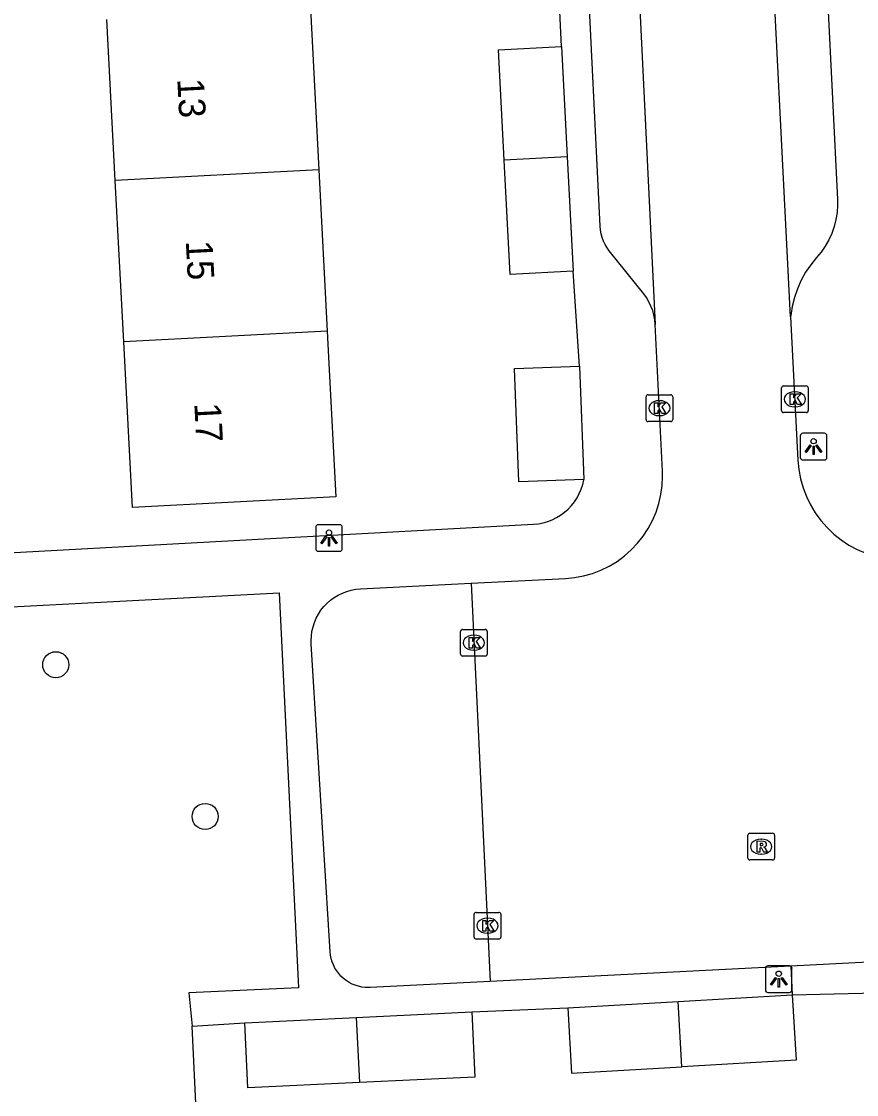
# Model space of a CAD drawing. Extents: x 161084 to 161928, y 385355 to 386522.
# Drawn here: x 161567.76 to 161599.07, y 385663.68 to 385703.9 of the extents above; entities that cross this region are included whole.
import ezdxf

# ---------------------------------------------------------------- set-up
doc = ezdxf.new("R2010")
doc.units = 0
for name, color, linetype in [('IMGEO_Boom', 7, 'Continuous'), ('IMGEO_Groenvoorziening', 7, 'Continuous'), ('IMGEO_Hek', 7, 'Continuous'), ('IMGEO_Kolk', 7, 'Continuous'), ('IMGEO_Lichtpunt', 7, 'Continuous'), ('IMGEO_Pand', 7, 'Continuous'), ('IMGEO_Pand_nummerreeks', 7, 'Continuous'), ('IMGEO_Rijbaan_lokaal_open', 7, 'Continuous'), ('IMGEO_Rioolput', 7, 'Continuous'), ('IMGEO_Voetpad_open', 7, 'Continuous')]:
    doc.layers.add(name, color=color, linetype=linetype)

msp = doc.modelspace()

# ---------------------------------------------------------------- linework, layer by layer
at = {"layer": 'IMGEO_Boom'}
for centre in [(161569.044, 385679.792), (161574.644, 385674.104)]:
    msp.add_circle(centre, 0.489, dxfattribs=at)
at = {"layer": 'IMGEO_Groenvoorziening'}
msp.add_lwpolyline([(161574.665, 385655.497), (161574.152, 385666.247)], dxfattribs=at)
at = {"layer": 'IMGEO_Hek'}
msp.add_lwpolyline([(161574.665, 385655.497), (161574.152, 385666.247)], dxfattribs=at)
at = {"layer": 'IMGEO_Kolk'}
for p, q in [((161596.255, 385689.315), (161596.255, 385690.167)), ((161596.33, 385690.241), (161597.182, 385690.241)), ((161597.256, 385690.167), (161597.256, 385689.315)), ((161591.174, 385688.982), (161591.174, 385689.834)), ((161591.249, 385689.908), (161592.101, 385689.908)), ((161591.662, 385689.688), (161591.687, 385689.688)), ((161592.175, 385689.834), (161592.175, 385688.982)), ((161596.743, 385690.021), (161596.768, 385690.021)), ((161596.766, 385689.461), (161596.741, 385689.461)), ((161592.101, 385688.908), (161591.249, 385688.908)), ((161591.685, 385689.128), (161591.66, 385689.128)), ((161597.182, 385689.241), (161596.33, 385689.241)), ((161584.22, 385680.189), (161584.22, 385681.041)), ((161584.295, 385681.115), (161585.147, 385681.115)), ((161584.708, 385680.895), (161584.733, 385680.895)), ((161585.221, 385681.041), (161585.221, 385680.189)), ((161585.147, 385680.115), (161584.295, 385680.115)), ((161584.731, 385680.335), (161584.706, 385680.335)), ((161584.73, 385669.585), (161584.73, 385670.437)), ((161584.805, 385670.511), (161585.657, 385670.511)), ((161585.731, 385670.437), (161585.731, 385669.585)), ((161585.218, 385670.291), (161585.243, 385670.291)), ((161585.241, 385669.731), (161585.216, 385669.731)), ((161585.657, 385669.511), (161584.805, 385669.511))]:
    msp.add_line(p, q, dxfattribs=at)
for points in [[(161596.255, 385689.315), (161596.255, 385690.167)], [(161596.33, 385690.241), (161597.182, 385690.241)], [(161597.256, 385690.167), (161597.256, 385689.315)], [(161591.174, 385688.982), (161591.174, 385689.834)], [(161591.249, 385689.908), (161592.101, 385689.908)], [(161592.175, 385689.834), (161592.175, 385688.982)], [(161596.576, 385689.941), (161596.699, 385689.941), (161596.699, 385689.79), (161596.829, 385689.941), (161596.993, 385689.941), (161596.847, 385689.79), (161597, 385689.541), (161596.848, 385689.541), (161596.763, 385689.705), (161596.699, 385689.638), (161596.699, 385689.541), (161596.576, 385689.541), (161596.576, 385689.941)], [(161591.495, 385689.608), (161591.618, 385689.608), (161591.618, 385689.457), (161591.748, 385689.608), (161591.912, 385689.608), (161591.766, 385689.457), (161591.919, 385689.208), (161591.767, 385689.208), (161591.682, 385689.372), (161591.618, 385689.305), (161591.618, 385689.208), (161591.495, 385689.208), (161591.495, 385689.608)], [(161592.101, 385688.908), (161591.249, 385688.908)], [(161597.182, 385689.241), (161596.33, 385689.241)], [(161584.22, 385680.189), (161584.22, 385681.041)], [(161584.295, 385681.115), (161585.147, 385681.115)], [(161584.541, 385680.815), (161584.664, 385680.815), (161584.664, 385680.664), (161584.794, 385680.815), (161584.958, 385680.815), (161584.812, 385680.664), (161584.965, 385680.415), (161584.813, 385680.415), (161584.728, 385680.579), (161584.664, 385680.512), (161584.664, 385680.415), (161584.541, 385680.415), (161584.541, 385680.815)], [(161585.221, 385681.041), (161585.221, 385680.189)], [(161585.147, 385680.115), (161584.295, 385680.115)], [(161584.73, 385669.585), (161584.73, 385670.437)], [(161584.805, 385670.511), (161585.657, 385670.511)], [(161585.731, 385670.437), (161585.731, 385669.585)], [(161585.051, 385670.211), (161585.174, 385670.211), (161585.174, 385670.06), (161585.304, 385670.211), (161585.468, 385670.211), (161585.322, 385670.06), (161585.475, 385669.811), (161585.323, 385669.811), (161585.238, 385669.975), (161585.174, 385669.908), (161585.174, 385669.811), (161585.051, 385669.811), (161585.051, 385670.211)], [(161585.657, 385669.511), (161584.805, 385669.511)]]:
    msp.add_lwpolyline(points, dxfattribs=at)
for centre, start, end in [((161596.332, 385690.165), 91.552, 178.448), ((161596.332, 385690.165), 91.552, 178.448), ((161597.18, 385690.165), 1.552, 88.448), ((161597.18, 385690.165), 1.552, 88.448), ((161591.251, 385689.832), 91.552, 178.448), ((161591.251, 385689.832), 91.552, 178.448), ((161592.099, 385689.832), 1.552, 88.448), ((161592.099, 385689.832), 1.552, 88.448), ((161596.332, 385689.317), 181.552, 268.448), ((161596.332, 385689.317), 181.552, 268.448), ((161597.18, 385689.317), 271.552, 358.448), ((161597.18, 385689.317), 271.552, 358.448), ((161591.251, 385688.984), 181.552, 268.448), ((161591.251, 385688.984), 181.552, 268.448), ((161592.099, 385688.984), 271.552, 358.448), ((161592.099, 385688.984), 271.552, 358.448), ((161584.297, 385681.039), 91.552, 178.448), ((161584.297, 385681.039), 91.552, 178.448), ((161585.145, 385681.039), 1.552, 88.448), ((161585.145, 385681.039), 1.552, 88.448), ((161584.297, 385680.191), 181.552, 268.448), ((161584.297, 385680.191), 181.552, 268.448), ((161585.145, 385680.191), 271.552, 358.448), ((161585.145, 385680.191), 271.552, 358.448), ((161584.807, 385670.435), 91.552, 178.448), ((161584.807, 385670.435), 91.552, 178.448), ((161585.655, 385670.435), 1.552, 88.448), ((161585.655, 385670.435), 1.552, 88.448), ((161584.807, 385669.587), 181.552, 268.448), ((161584.807, 385669.587), 181.552, 268.448), ((161585.655, 385669.587), 271.552, 358.448), ((161585.655, 385669.587), 271.552, 358.448)]:
    msp.add_arc(centre, 0.0765, start, end, dxfattribs=at)
for centre, major_axis, ratio, start_param, end_param in [((161591.661, 385689.408), (-0.387, 0.002), 0.722429, 4.712389, 7.853982), ((161591.686, 385689.408), (-0.39, 0.002), 0.717154, 1.570796, 4.712389), ((161596.742, 385689.741), (-0.387, 0.002), 0.722429, 4.712389, 7.853982), ((161596.767, 385689.741), (-0.39, 0.002), 0.717154, 1.570796, 4.712389), ((161584.707, 385680.615), (-0.387, 0.002), 0.722429, 4.712389, 7.853982), ((161584.732, 385680.615), (-0.39, 0.002), 0.717154, 1.570796, 4.712389), ((161585.217, 385670.011), (-0.387, 0.002), 0.722429, 4.712389, 7.853982), ((161585.242, 385670.011), (-0.39, 0.002), 0.717154, 1.570796, 4.712389)]:
    msp.add_ellipse(centre, major_axis=major_axis, ratio=ratio, start_param=start_param, end_param=end_param, dxfattribs=at)
at = {"layer": 'IMGEO_Lichtpunt'}
for p, q in [((161597.861, 385688.466), (161597.053, 385688.466)), ((161597.861, 385688.466), (161597.053, 385688.466)), ((161596.959, 385688.371), (161596.959, 385687.564)), ((161596.959, 385688.371), (161596.959, 385687.564)), ((161597.955, 385687.564), (161597.955, 385688.371)), ((161597.955, 385687.564), (161597.955, 385688.371)), ((161597.053, 385687.47), (161597.861, 385687.47)), ((161597.053, 385687.47), (161597.861, 385687.47)), ((161578.789, 385684.944), (161578.789, 385684.137)), ((161578.789, 385684.944), (161578.789, 385684.137)), ((161579.691, 385685.039), (161578.883, 385685.039)), ((161579.691, 385685.039), (161578.883, 385685.039)), ((161579.785, 385684.137), (161579.785, 385684.944)), ((161579.785, 385684.137), (161579.785, 385684.944)), ((161578.883, 385684.043), (161579.691, 385684.043)), ((161578.883, 385684.043), (161579.691, 385684.043)), ((161595.651, 385668.411), (161595.651, 385667.604)), ((161595.651, 385668.411), (161595.651, 385667.604)), ((161596.553, 385668.506), (161595.745, 385668.506)), ((161596.553, 385668.506), (161595.745, 385668.506)), ((161596.647, 385667.604), (161596.647, 385668.411)), ((161596.647, 385667.604), (161596.647, 385668.411)), ((161595.745, 385667.51), (161596.553, 385667.51)), ((161595.745, 385667.51), (161596.553, 385667.51))]:
    msp.add_line(p, q, dxfattribs=at)
for points in [[(161597.333, 385688.035), (161597.372, 385688.007), (161597.184, 385687.745), (161597.146, 385687.772), (161597.333, 385688.035)], [(161597.435, 385687.987), (161597.482, 385687.987), (161597.482, 385687.665), (161597.435, 385687.665), (161597.435, 385687.987)], [(161597.545, 385688.007), (161597.583, 385688.034), (161597.77, 385687.772), (161597.731, 385687.744), (161597.545, 385688.007)], [(161579.163, 385684.608), (161579.202, 385684.58), (161579.014, 385684.318), (161578.976, 385684.345), (161579.163, 385684.608)], [(161579.265, 385684.56), (161579.312, 385684.56), (161579.312, 385684.238), (161579.265, 385684.238), (161579.265, 385684.56)], [(161579.375, 385684.58), (161579.413, 385684.607), (161579.6, 385684.345), (161579.561, 385684.317), (161579.375, 385684.58)], [(161596.025, 385668.075), (161596.064, 385668.047), (161595.876, 385667.785), (161595.838, 385667.812), (161596.025, 385668.075)], [(161596.127, 385668.027), (161596.174, 385668.027), (161596.174, 385667.705), (161596.127, 385667.705), (161596.127, 385668.027)], [(161596.237, 385668.047), (161596.275, 385668.074), (161596.462, 385667.812), (161596.423, 385667.784), (161596.237, 385668.047)]]:
    msp.add_lwpolyline(points, dxfattribs=at)
for centre in [(161597.458, 385688.169), (161579.288, 385684.742), (161596.15, 385668.209)]:
    msp.add_circle(centre, 0.0994, dxfattribs=at)
for centre, start, end in [((161597.053, 385688.371), 90, 180), ((161597.053, 385688.371), 90, 180), ((161597.861, 385688.371), 0, 90), ((161597.861, 385688.371), 0, 90), ((161597.053, 385687.564), 180, 270), ((161597.053, 385687.564), 180, 270), ((161597.861, 385687.564), 270, 0), ((161597.861, 385687.564), 270, 360), ((161578.883, 385684.944), 90, 180), ((161578.883, 385684.944), 90, 180), ((161579.691, 385684.944), 0, 90), ((161579.691, 385684.944), 0, 90), ((161578.883, 385684.137), 180, 270), ((161578.883, 385684.137), 180, 270), ((161579.691, 385684.137), 270, 0), ((161579.691, 385684.137), 270, 360), ((161595.745, 385668.411), 90, 180), ((161595.745, 385668.411), 90, 180), ((161596.553, 385668.411), 0, 90), ((161596.553, 385668.411), 0, 90), ((161595.745, 385667.604), 180, 270), ((161595.745, 385667.604), 180, 270), ((161596.553, 385667.604), 270, 0), ((161596.553, 385667.604), 270, 360)]:
    msp.add_arc(centre, 0.0946, start, end, dxfattribs=at)
at = {"layer": 'IMGEO_Pand'}
for points in [[(161578.591, 385704.38), (161578.908, 385698.338)], [(161571.276, 385697.937), (161570.959, 385703.979)], [(161585.857, 385698.703), (161585.64, 385702.842), (161588.001, 385702.965)], [(161588.001, 385702.965), (161588.218, 385698.827)], [(161588.218, 385698.827), (161585.857, 385698.703)], [(161588.442, 385694.537), (161586.081, 385694.414), (161585.857, 385698.703)], [(161588.218, 385698.827), (161588.442, 385694.537)], [(161578.908, 385698.338), (161571.276, 385697.937)], [(161578.908, 385698.338), (161579.224, 385692.297)], [(161571.592, 385691.896), (161571.276, 385697.937)], [(161579.224, 385692.297), (161579.288, 385691.076), (161579.55, 385686.082), (161571.918, 385685.682), (161571.592, 385691.896)], [(161579.224, 385692.297), (161571.592, 385691.896)], [(161588.842, 385686.74), (161586.4, 385686.65), (161586.244, 385690.896), (161588.686, 385690.985)], [(161588.686, 385690.985), (161588.842, 385686.74)], [(161588.24, 385666.927), (161592.381, 385667.168)], [(161592.381, 385667.168), (161596.66, 385667.416)], [(161592.512, 385664.723), (161592.381, 385667.168)], [(161596.66, 385667.416), (161596.802, 385664.972), (161592.512, 385664.723)], [(161580.304, 385666.571), (161584.639, 385666.778)], [(161584.639, 385666.778), (161584.756, 385664.336), (161580.434, 385664.13)], [(161588.24, 385666.927), (161588.382, 385664.483), (161592.512, 385664.723)], [(161576.129, 385666.372), (161580.304, 385666.571)], [(161580.434, 385664.13), (161576.245, 385663.93), (161576.129, 385666.372)], [(161580.304, 385666.571), (161580.434, 385664.13)]]:
    msp.add_lwpolyline(points, dxfattribs=at)
at = {"layer": 'IMGEO_Rijbaan_lokaal_open'}
for points in [[(161596.596, 385692.828), (161594.088, 385742.233)], [(161589.157, 385741.137), (161591.522, 385692.541)], [(161584.616, 385682.847), (161588.158, 385683.027), (161588.499, 385683.06), (161588.836, 385683.123), (161589.166, 385683.216), (161589.486, 385683.337), (161589.794, 385683.488), (161590.087, 385683.665), (161590.364, 385683.867), (161590.621, 385684.093), (161590.857, 385684.342), (161591.07, 385684.61), (161591.258, 385684.897), (161591.42, 385685.199), (161591.554, 385685.514), (161591.659, 385685.84), (161591.735, 385686.175), (161591.781, 385686.514), (161591.796, 385686.857), (161591.791, 385687.042), (161591.522, 385692.541)], [(161596.596, 385692.828), (161596.869, 385687.458), (161596.902, 385687.108), (161596.966, 385686.763), (161597.061, 385686.425), (161597.186, 385686.096), (161597.34, 385685.78), (161597.521, 385685.479), (161597.728, 385685.195), (161597.96, 385684.931), (161598.215, 385684.689), (161598.49, 385684.471), (161598.783, 385684.278), (161599.093, 385684.112), (161599.416, 385683.974), (161599.751, 385683.866), (161600.093, 385683.788), (161600.441, 385683.74), (161600.792, 385683.725), (161600.978, 385683.729), (161604.502, 385683.896)], [(161584.616, 385682.847), (161585.333, 385667.917)], [(161605.307, 385668.948), (161596.604, 385668.499)], [(161596.604, 385668.499), (161585.333, 385667.917)]]:
    msp.add_lwpolyline(points, dxfattribs=at)
at = {"layer": 'IMGEO_Rioolput'}
for p, q in [((161594.995, 385672.547), (161594.995, 385673.399)), ((161595.07, 385673.473), (161595.922, 385673.473)), ((161595.483, 385673.253), (161595.508, 385673.253)), ((161595.996, 385673.399), (161595.996, 385672.547)), ((161595.922, 385672.473), (161595.07, 385672.473)), ((161595.506, 385672.693), (161595.481, 385672.693))]:
    msp.add_line(p, q, dxfattribs=at)
for points in [[(161594.995, 385672.547), (161594.995, 385673.399)], [(161595.07, 385673.473), (161595.922, 385673.473)], [(161595.584, 385673.171), (161595.332, 385673.173), (161595.332, 385672.773)], [(161595.996, 385673.399), (161595.996, 385672.547)], [(161595.332, 385672.773), (161595.456, 385672.773), (161595.456, 385672.935), (161595.467, 385672.935)], [(161595.51, 385673.092), (161595.456, 385673.092), (161595.456, 385673.011)], [(161595.456, 385673.011), (161595.508, 385673.011)], [(161595.514, 385672.906), (161595.585, 385672.773), (161595.725, 385672.773), (161595.66, 385672.899)], [(161595.922, 385672.473), (161595.07, 385672.473)]]:
    msp.add_lwpolyline(points, dxfattribs=at)
for centre, radius, start, end in [((161595.072, 385673.397), 0.0765, 91.552, 178.448), ((161595.072, 385673.397), 0.0765, 91.552, 178.448), ((161595.583, 385673.061), 0.109, 350.3612, 89.416), ((161595.92, 385673.397), 0.0765, 1.552, 88.448), ((161595.92, 385673.397), 0.0765, 1.552, 88.448), ((161595.466, 385672.882), 0.0533, 26.0293, 88.6989), ((161595.492, 385673.2), 0.19, 274.7715, 282.9687), ((161595.516, 385672.996), 0.0964, 77.0061, 93.1865), ((161595.53, 385673.053), 0.0378, 276.6634, 79.6772), ((161595.581, 385673.061), 0.112, 277.5842, 350.9817), ((161595.565, 385672.846), 0.108, 29.5134, 73.7905), ((161595.072, 385672.549), 0.0765, 181.552, 268.448), ((161595.072, 385672.549), 0.0765, 181.552, 268.448), ((161595.92, 385672.549), 0.0765, 271.552, 358.448), ((161595.92, 385672.549), 0.0765, 271.552, 358.448)]:
    msp.add_arc(centre, radius, start, end, dxfattribs=at)
for centre, major_axis, ratio, start_param, end_param in [((161595.482, 385672.973), (-0.387, 0.002), 0.722429, 4.712389, 7.853982), ((161595.507, 385672.973), (-0.39, 0.002), 0.717154, 1.570796, 4.712389)]:
    msp.add_ellipse(centre, major_axis=major_axis, ratio=ratio, start_param=start_param, end_param=end_param, dxfattribs=at)
at = {"layer": 'IMGEO_Voetpad_open'}
for points in [[(161597.785, 385708.561), (161598.352, 385697.225), (161598.355, 385697.013), (161598.336, 385696.744), (161598.294, 385696.477), (161598.228, 385696.215), (161598.139, 385695.96), (161598.028, 385695.714), (161597.895, 385695.479), (161597.742, 385695.257), (161597.569, 385695.049), (161597.35, 385694.783), (161597.156, 385694.499), (161596.988, 385694.199), (161596.848, 385693.884), (161596.736, 385693.559), (161596.654, 385693.224), (161596.602, 385692.884), (161596.596, 385692.828)], [(161588.001, 385702.965), (161587.828, 385706.631)], [(161591.522, 385692.541), (161591.505, 385692.719), (161591.473, 385692.895), (161591.424, 385693.068), (161591.361, 385693.235), (161591.283, 385693.396), (161591.191, 385693.55), (161591.087, 385693.692), (161589.798, 385695.305), (161589.715, 385695.419), (161589.641, 385695.542), (161589.578, 385695.671), (161589.527, 385695.804), (161589.489, 385695.942), (161589.463, 385696.083), (161589.449, 385696.226), (161588.938, 385706.681)], [(161588.686, 385690.985), (161588.442, 385694.537)], [(161563.603, 385683.786), (161577.326, 385684.534), (161586.958, 385685.059), (161587.138, 385685.077), (161587.315, 385685.11), (161587.489, 385685.16), (161587.658, 385685.225), (161587.82, 385685.304), (161587.974, 385685.398), (161588.12, 385685.505), (161588.255, 385685.625), (161588.379, 385685.756), (161588.491, 385685.898), (161588.59, 385686.049), (161588.674, 385686.209), (161588.745, 385686.375), (161588.8, 385686.547), (161588.839, 385686.724), (161588.842, 385686.74)], [(161585.333, 385667.917), (161580.829, 385667.693), (161580.774, 385667.691), (161580.646, 385667.696), (161580.519, 385667.711), (161580.394, 385667.738), (161580.272, 385667.776), (161580.154, 385667.825), (161580.041, 385667.884), (161579.933, 385667.953), (161579.832, 385668.031), (161579.738, 385668.118), (161579.653, 385668.214), (161579.576, 385668.316), (161579.509, 385668.425), (161579.452, 385668.539), (161579.405, 385668.658), (161579.369, 385668.781), (161579.345, 385668.906), (161579.331, 385669.033), (161578.623, 385680.576), (161578.619, 385680.694), (161578.627, 385680.868), (161578.65, 385681.04), (161578.689, 385681.21), (161578.742, 385681.375), (161578.81, 385681.535), (161578.892, 385681.689), (161578.988, 385681.834), (161579.096, 385681.97), (161579.215, 385682.096), (161579.346, 385682.211), (161579.486, 385682.314), (161579.635, 385682.403), (161579.791, 385682.48), (161579.954, 385682.541), (161580.121, 385682.588), (161580.292, 385682.62), (161580.465, 385682.637), (161584.616, 385682.847)], [(161563.779, 385681.769), (161577.425, 385682.484), (161578.14, 385667.677), (161574.03, 385667.491), (161574.152, 385666.247)], [(161596.604, 385668.499), (161596.66, 385667.416)], [(161596.66, 385667.416), (161600.328, 385667.504)], [(161584.639, 385666.778), (161588.24, 385666.927)], [(161574.152, 385666.247), (161576.129, 385666.372)]]:
    msp.add_lwpolyline(points, dxfattribs=at)

# ---------------------------------------------------------------- texts
at = {"layer": 'IMGEO_Pand_nummerreeks'}
for s, p in [('13', (161573.599, 385701.748)), ('15', (161573.918, 385695.668)), ('17', (161574.237, 385689.588))]:
    msp.add_text(s, height=1, rotation=273.0001, dxfattribs=at).set_placement(p)

doc.saveas('drawing.dxf')
